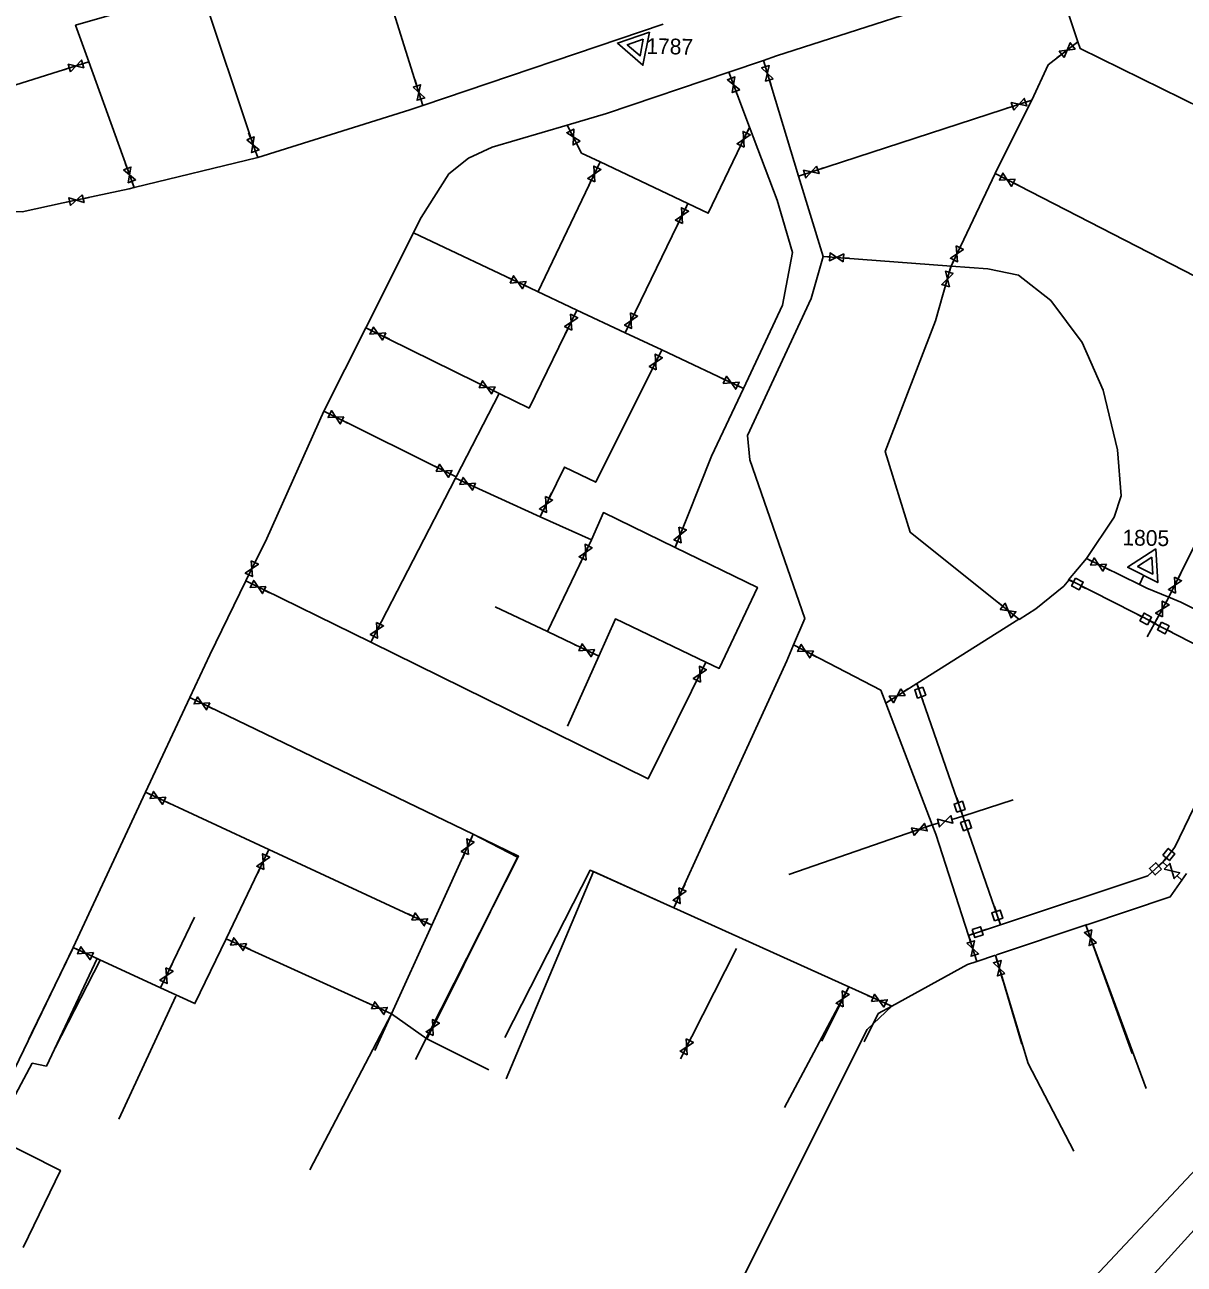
# Model space of a CAD drawing. Extents: x 349903 to 372392, y 368574 to 383062.
# Drawn here: x 362470.3 to 362839.3, y 371926.1 to 372320.7 of the extents above; entities that cross this region are included whole.
import ezdxf

# ---------------------------------------------------------------- set-up
doc = ezdxf.new("R2010")
doc.units = 0
for name, color, linetype in [('Niveau 1', 7, 'Continuous'), ('Niveau 10', 7, 'Continuous'), ('Niveau 2', 7, 'Continuous'), ('Niveau 3', 7, 'Continuous')]:
    doc.layers.add(name, color=color, linetype=linetype)

msp = doc.modelspace()

# ---------------------------------------------------------------- linework, layer by layer
at = {"layer": 'Niveau 1'}
for p, q in [((362805.444, 372315.204), (362803.772, 372313.927)), ((362490.677, 372308.847), (362488.668, 372308.22)), ((362705.358, 372309.317), (362705.968, 372307.303)), ((362800.292, 372311.267), (362798.781, 372310.113)), ((362484.488, 372306.914), (362482.673, 372306.347)), ((362694.347, 372305.592), (362695.081, 372303.62)), ((362595.067, 372301.2), (362594.506, 372303.017)), ((362707.238, 372303.111), (362707.789, 372301.292)), ((362596.98, 372295.005), (362596.359, 372297.016)), ((362696.61, 372299.516), (362697.274, 372297.734)), ((362790.786, 372296.717), (362788.788, 372296.057)), ((362784.629, 372294.684), (362782.824, 372294.087)), ((362642.871, 372288.726), (362643.845, 372286.86)), ((362542.151, 372284.521), (362541.493, 372286.305)), ((362700.947, 372288.086), (362700.029, 372286.192)), ((362544.393, 372278.437), (362543.666, 372280.412)), ((362645.872, 372282.978), (362646.752, 372281.293)), ((362698.121, 372282.251), (362697.292, 372280.539)), ((362502.855, 372274.922), (362502.19, 372276.703)), ((362653.4, 372277.031), (362652.482, 372275.138)), ((362716.495, 372272.477), (362718.496, 372273.128)), ((362722.66, 372274.485), (362724.468, 372275.074)), ((362779.135, 372273.306), (362781.006, 372272.343)), ((362505.124, 372268.848), (362504.388, 372270.819)), ((362650.571, 372271.197), (362649.742, 372269.486)), ((362784.901, 372270.34), (362786.592, 372269.471)), ((362488.854, 372265.294), (362490.713, 372265.694)), ((362482.515, 372263.933), (362484.572, 372264.374)), ((362681.331, 372263.756), (362680.408, 372261.865)), ((362678.488, 372257.928), (362677.655, 372256.219)), ((362767.884, 372249.716), (362768.707, 372251.43)), ((362724.348, 372246.944), (362726.447, 372246.792)), ((362730.815, 372246.476), (362732.711, 372246.339)), ((362765.079, 372243.87), (362765.99, 372245.767)), ((362765.079, 372243.87), (362764.502, 372241.846)), ((362625.31, 372239.612), (362623.589, 372240.419)), ((362631.181, 372236.86), (362629.276, 372237.754)), ((362763.303, 372237.634), (362762.782, 372235.805)), ((362646.021, 372229.865), (362645.101, 372227.973)), ((362664.179, 372228.474), (362665.003, 372230.187)), ((362578.773, 372224.214), (362580.671, 372223.305)), ((362584.622, 372221.415), (362586.337, 372220.595)), ((362643.187, 372224.033), (362642.355, 372222.323)), ((362661.368, 372222.631), (362662.281, 372224.527)), ((362672.993, 372217.152), (362672.06, 372215.266)), ((362670.119, 372211.34), (362669.276, 372209.636)), ((362615.448, 372206.206), (362613.743, 372207.047)), ((362693.115, 372207.655), (362691.394, 372208.462)), ((362698.985, 372204.9), (362697.08, 372205.794)), ((362621.264, 372203.339), (362619.377, 372204.27)), ((362565.47, 372197.694), (362567.345, 372196.738)), ((362571.247, 372194.749), (362572.941, 372193.886)), ((362601.751, 372179.642), (362600.048, 372180.488)), ((362607.558, 372176.757), (362605.674, 372177.694)), ((362607.33, 372176.314), (362609.247, 372175.446)), ((362613.237, 372173.641), (362614.969, 372172.857)), ((362637.098, 372169.922), (362637.923, 372171.635)), ((362634.284, 372164.08), (362635.197, 372165.976)), ((362679.66, 372160.312), (362680.364, 372162.078)), ((362650.612, 372156.662), (362649.704, 372154.764)), ((362677.261, 372154.288), (362678.04, 372156.243)), ((362543.494, 372149.477), (362544.32, 372151.189)), ((362647.815, 372150.812), (362646.995, 372149.097)), ((362808.128, 372150.757), (362810.011, 372149.818)), ((362813.931, 372147.865), (362815.633, 372147.017)), ((362540.677, 372143.637), (362541.592, 372145.532)), ((362540.677, 372143.637), (362542.554, 372142.686)), ((362837.3, 372144.245), (362838.145, 372145.949)), ((362546.462, 372140.71), (362548.158, 372139.851)), ((362834.42, 372138.436), (362833.401, 372136.595)), ((362834.42, 372138.436), (362835.355, 372140.321)), ((362781.534, 372135.548), (362780.049, 372136.735)), ((362583.346, 372129.866), (362584.21, 372131.56)), ((362786.598, 372131.498), (362784.955, 372132.813)), ((362831.281, 372132.763), (362830.362, 372131.099)), ((362580.402, 372124.089), (362581.358, 372125.964)), ((362647.1, 372122.491), (362645.382, 372123.306)), ((362714.946, 372123.279), (362716.806, 372122.296)), ((362652.959, 372119.713), (362651.058, 372120.615)), ((362720.679, 372120.25), (362722.36, 372119.362)), ((362687.029, 372117.794), (362686.097, 372115.907)), ((362684.159, 372111.98), (362683.318, 372110.275)), ((362749.741, 372108.234), (362751.348, 372109.251)), ((362522.808, 372106.511), (362524.701, 372105.592)), ((362528.642, 372103.682), (362530.353, 372102.852)), ((362744.262, 372104.767), (362746.04, 372105.892)), ((362508.747, 372076.346), (362510.656, 372075.46)), ((362514.629, 372073.618), (362516.354, 372072.818)), ((362765.298, 372067.722), (362767.128, 372068.237)), ((362752.938, 372063.817), (362751.145, 372063.186)), ((362759.055, 372065.969), (362757.07, 372065.271)), ((362759.055, 372065.969), (362761.081, 372066.538)), ((362612.976, 372062.964), (362612.12, 372061.042)), ((362547.981, 372058.132), (362547.082, 372056.229)), ((362610.339, 372057.04), (362609.566, 372055.303)), ((362545.211, 372052.269), (362544.399, 372050.55)), ((362833.805, 372052.811), (362832.422, 372054.116)), ((362838.519, 372048.359), (362836.989, 372049.804)), ((362679.603, 372045.408), (362680.407, 372047.131)), ((362676.861, 372039.532), (362677.751, 372041.439)), ((362593.982, 372036.818), (362592.262, 372037.628)), ((362599.847, 372034.053), (362597.944, 372034.951)), ((362807.96, 372034.098), (362808.672, 372032.118)), ((362534.352, 372029.732), (362536.275, 372028.877)), ((362771.327, 372028.691), (362770.759, 372030.506)), ((362810.154, 372027.997), (362810.798, 372026.208)), ((362485.697, 372026.903), (362487.607, 372026.02)), ((362491.584, 372024.185), (362493.31, 372023.388)), ((362540.278, 372027.1), (362542.015, 372026.328)), ((362773.262, 372022.503), (362772.634, 372024.512)), ((362779.161, 372024.474), (362779.764, 372022.458)), ((362516.335, 372019.929), (362517.169, 372021.637)), ((362513.488, 372014.103), (362514.412, 372015.994)), ((362781.02, 372018.262), (362781.566, 372016.441)), ((362732.486, 372014.468), (362731.551, 372012.583)), ((362581.13, 372008.519), (362579.399, 372009.305)), ((362729.606, 372008.659), (362728.761, 372006.955)), ((362740.247, 372010.925), (362738.508, 372011.694)), ((362746.176, 372008.3), (362744.252, 372009.152)), ((362587.035, 372005.84), (362585.119, 372006.71)), ((362602.101, 372005.269), (362601.126, 372003.405)), ((362599.095, 371999.524), (362598.214, 371997.84)), ((362681.943, 371997.286), (362682.806, 371998.98)), ((362681.943, 371997.286), (362682.806, 371998.98)), ((362678.999, 371991.509), (362679.954, 371993.383)), ((362678.999, 371991.509), (362679.954, 371993.383))]:
    msp.add_line(p, q, dxfattribs=at)
for points in [[(362801.065, 372310.262), (362799.527, 372312.262), (362804.531, 372312.91), (362803.005, 372314.92)], [(362484.87, 372305.704), (362484.11, 372308.111), (362489.033, 372307.005), (362488.288, 372309.416)], [(362697.797, 372299.962), (362695.435, 372299.074), (362696.275, 372304.05), (362693.907, 372303.176)], [(362708.45, 372303.483), (362706.038, 372302.744), (362707.186, 372307.657), (362704.768, 372306.933)], [(362593.856, 372300.822), (362596.265, 372301.574), (362595.143, 372296.655), (362597.557, 372297.392)], [(362785.031, 372293.481), (362784.232, 372295.874), (362789.172, 372294.849), (362788.389, 372297.247)], [(362540.962, 372284.079), (362543.327, 372284.959), (362542.471, 372279.986), (362544.841, 372280.851)], [(362646.994, 372283.569), (362644.761, 372282.394), (362644.975, 372287.435), (362642.735, 372286.274)], [(362699.264, 372281.701), (362696.989, 372282.794), (362701.165, 372285.627), (362698.897, 372286.734)], [(362501.669, 372274.475), (362504.03, 372275.365), (362503.195, 372270.389), (362505.562, 372271.264)], [(362651.714, 372270.647), (362649.44, 372271.741), (362653.617, 372274.572), (362651.35, 372275.68)], [(362722.264, 372275.69), (362723.053, 372273.293), (362718.116, 372274.339), (362718.89, 372271.937)], [(362785.477, 372271.47), (362784.33, 372269.222), (362781.599, 372273.465), (362780.437, 372271.224)], [(362488.584, 372266.533), (362489.122, 372264.068), (362484.32, 372265.618), (362484.842, 372263.149)], [(362679.63, 372257.376), (362677.359, 372258.475), (362681.542, 372261.296), (362679.278, 372262.41)], [(362766.739, 372250.261), (362769.018, 372249.176), (362764.852, 372246.328), (362767.124, 372245.229)], [(362730.902, 372247.741), (362730.728, 372245.224), (362726.552, 372248.056), (362726.362, 372245.54)], [(362764.524, 372237.29), (362762.094, 372237.974), (362765.718, 372241.486), (362763.293, 372242.185)], [(362624.776, 372238.462), (362625.839, 372240.75), (362628.725, 372236.611), (362629.803, 372238.892)], [(362663.035, 372229.02), (362665.312, 372227.933), (362661.144, 372225.09), (362663.414, 372223.988)], [(362644.329, 372223.483), (362642.056, 372224.579), (362646.236, 372227.406), (362643.969, 372228.516)], [(362585.165, 372222.561), (362584.083, 372220.281), (362581.231, 372224.444), (362580.135, 372222.171)], [(362671.257, 372210.781), (362668.992, 372211.893), (362673.191, 372214.691), (362670.932, 372215.817)], [(362614.892, 372205.068), (362616, 372207.334), (362618.804, 372203.138), (362619.926, 372205.398)], [(362692.58, 372206.505), (362693.645, 372208.793), (362696.529, 372204.652), (362697.608, 372206.933)], [(362571.819, 372195.881), (362570.68, 372193.629), (362567.933, 372197.862), (362566.78, 372195.617)], [(362601.191, 372178.505), (362602.306, 372180.768), (362605.097, 372176.564), (362606.227, 372178.82)], [(362613.756, 372174.798), (362612.723, 372172.496), (362609.783, 372176.596), (362608.735, 372174.3)], [(362635.953, 372170.468), (362638.23, 372169.381), (362634.061, 372166.539), (362636.331, 372165.436)], [(362678.481, 372160.777), (362680.828, 372159.851), (362676.867, 372156.725), (362679.208, 372155.784)], [(362648.961, 372150.269), (362646.681, 372151.35), (362650.842, 372154.204), (362648.569, 372155.3)], [(362814.493, 372149.001), (362813.375, 372146.74), (362810.589, 372150.947), (362809.457, 372148.692)], [(362542.351, 372150.024), (362544.627, 372148.935), (362540.455, 372146.096), (362542.725, 372144.992)], [(362547.031, 372141.842), (362545.899, 372139.587), (362543.14, 372143.812), (362541.993, 372141.564)], [(362836.162, 372144.805), (362838.426, 372143.691), (362834.225, 372140.897), (362836.482, 372139.769)], [(362780.745, 372134.555), (362782.315, 372136.53), (362784.152, 372131.831), (362785.734, 372133.796)], [(362832.393, 372132.152), (362830.182, 372133.366), (362834.504, 372135.969), (362832.3, 372137.197)], [(362582.215, 372130.438), (362584.466, 372129.299), (362580.234, 372126.552), (362582.479, 372125.399)], [(362646.561, 372121.344), (362647.635, 372123.627), (362650.502, 372119.475), (362651.59, 372121.752)], [(362721.268, 372121.373), (362720.096, 372119.139), (362717.411, 372123.411), (362716.225, 372121.183)], [(362685.298, 372111.422), (362683.032, 372112.532), (362687.229, 372115.333), (362684.969, 372116.457)], [(362529.192, 372104.824), (362528.098, 372102.551), (362525.267, 372106.728), (362524.159, 372104.461)], [(362749.059, 372109.304), (362750.416, 372107.176), (362745.374, 372106.971), (362746.716, 372104.835)], [(362515.159, 372074.77), (362514.105, 372072.478), (362511.202, 372076.605), (362510.133, 372074.319)], [(362764.951, 372068.942), (362765.641, 372066.515), (362760.751, 372067.762), (362761.426, 372065.331)], [(362753.363, 372062.622), (362752.518, 372065), (362757.478, 372064.07), (362756.648, 372066.453)], [(362611.499, 372056.528), (362609.191, 372057.547), (362613.273, 372060.513), (362610.971, 372061.547)], [(362546.36, 372051.731), (362544.075, 372052.802), (362548.223, 372055.675), (362545.944, 372056.76)], [(362832.937, 372051.886), (362834.664, 372053.726), (362836.108, 372048.891), (362837.847, 372050.721)], [(362678.452, 372045.94), (362680.742, 372044.881), (362676.608, 372041.988), (362678.891, 372040.913)], [(362593.445, 372035.669), (362594.514, 372037.955), (362597.39, 372033.809), (362598.474, 372036.088)], [(362811.346, 372028.43), (362808.975, 372027.568), (362809.87, 372032.534), (362807.493, 372031.687)], [(362540.789, 372028.26), (362539.772, 372025.951), (362536.803, 372030.031), (362535.771, 372027.728)], [(362770.118, 372028.309), (362772.524, 372029.07), (362771.42, 372024.146), (362773.83, 372024.892)], [(362492.112, 372025.338), (362491.061, 372023.043), (362488.152, 372027.166), (362487.086, 372024.879)], [(362515.194, 372020.482), (362517.464, 372019.381), (362513.279, 372016.563), (362515.542, 372015.448)], [(362782.234, 372018.63), (362779.819, 372017.899), (362780.983, 372022.808), (362778.563, 372022.092)], [(362730.744, 372008.099), (362728.479, 372009.213), (362732.681, 372012.007), (362730.424, 372013.135)], [(362739.737, 372009.763), (362740.752, 372012.074), (362743.726, 372007.998), (362744.755, 372010.302)], [(362580.61, 372007.363), (362581.645, 372009.664), (362584.582, 372005.56), (362585.632, 372007.855)], [(362600.221, 371998.94), (362597.981, 372000.102), (362602.242, 372002.805), (362600.012, 372003.982)], [(362680.812, 371997.858), (362683.063, 371996.72), (362678.83, 371993.972), (362681.075, 371992.819)], [(362680.812, 371997.858), (362683.063, 371996.72), (362678.83, 371993.972), (362681.075, 371992.819)]]:
    msp.add_lwpolyline(points, close=True, dxfattribs=at)
at = {"layer": 'Niveau 10'}
for p, q in [((362579.032, 372352.421), (362596.98, 372295.005)), ((362490.677, 372308.847), (362453.772, 372297.302)), ((362653.4, 372277.031), (362633.58, 372235.591)), ((362681.331, 372263.756), (362661.368, 372222.631)), ((362631.181, 372236.86), (362593.955, 372254.407)), ((362646.021, 372229.865), (362631.181, 372236.86)), ((362661.368, 372222.631), (362646.021, 372229.865)), ((362672.993, 372217.152), (362661.368, 372222.631)), ((362698.985, 372204.9), (362672.993, 372217.152)), ((362621.264, 372203.339), (362607.558, 372176.757)), ((362565.47, 372197.694), (362607.558, 372176.757)), ((362607.33, 372176.314), (362580.402, 372124.089)), ((362607.558, 372176.757), (362607.33, 372176.314)), ((362650.612, 372156.662), (362636.6, 372127.5)), ((362826.383, 372145.423), (362825.007, 372142.487)), ((362834.42, 372138.436), (362829.807, 372130.063)), ((362636.6, 372127.5), (362620.024, 372135.391)), ((362652.959, 372119.713), (362636.6, 372127.5)), ((362829.807, 372130.063), (362827.458, 372125.797)), ((362768.799, 372068.779), (362754.175, 372111.026)), ((362547.981, 372058.132), (362508.747, 372076.346)), ((362768.799, 372068.779), (362784.87, 372073.992)), ((362767.128, 372068.237), (362768.799, 372068.779)), ((362780.775, 372034.184), (362768.799, 372068.779)), ((362759.055, 372065.969), (362713.453, 372050.181)), ((362612.976, 372062.964), (362599.847, 372034.053)), ((362599.847, 372034.053), (362547.981, 372058.132)), ((362513.488, 372014.103), (362524.282, 372036.571)), ((362599.847, 372034.053), (362587.035, 372005.84)), ((362807.96, 372034.098), (362827.199, 371982.008)), ((362807.96, 372034.098), (362822.709, 371993.212)), ((362534.352, 372029.732), (362587.035, 372005.84)), ((362485.697, 372026.903), (362444.861, 371942.512)), ((362679.003, 371991.508), (362696.817, 372026.648)), ((362779.161, 372024.474), (362787.571, 371996.15)), ((362732.486, 372014.468), (362712.068, 371976.03)), ((362732.486, 372014.468), (362723.989, 371997.144)), ((362518.364, 372011.498), (362500.19, 371972.271)), ((362587.035, 372005.84), (362560.985, 371956.13)), ((362587.035, 372005.84), (362581.728, 371994.153)), ((362587.035, 372005.84), (362598.214, 371997.84)), ((362598.214, 371997.84), (362618.01, 371987.97))]:
    msp.add_line(p, q, dxfattribs=at)
for points in [[(363758.548, 373021.97), (363387.656, 372576.394), (363076.85, 372194.567), (362987.022, 372096.447), (362639.639, 371713.502), (362501.408, 371562.226)], [(362797.375, 372339.552), (362805.444, 372315.204)], [(362786.658, 372335.779), (362780.961, 372333.773), (362709.546, 372310.734), (362705.358, 372309.317)], [(362526.463, 372332.136), (362486.468, 372320.502), (362490.677, 372308.847)], [(362526.463, 372332.136), (362543.088, 372282.102), (362544.393, 372278.437)], [(362673.495, 372320.892), (362596.98, 372295.005)], [(362805.444, 372315.204), (362795.945, 372307.922), (362790.786, 372296.717)], [(362805.444, 372315.204), (362806.153, 372313.063), (362877.34, 372278.055), (362886.07, 372267.956), (362910.619, 372195.537), (362908.232, 372180.436), (362896.579, 372157.215)], [(362490.677, 372308.847), (362505.124, 372268.848)], [(362705.358, 372309.317), (362694.347, 372305.592)], [(362705.358, 372309.317), (362716.495, 372272.477)], [(362694.347, 372305.592), (362655.434, 372292.43), (362642.871, 372288.726)], [(362694.347, 372305.592), (362700.947, 372288.086)], [(362790.786, 372296.717), (362716.495, 372272.477)], [(362790.786, 372296.717), (362781.328, 372277.9), (362779.135, 372273.306)], [(362596.98, 372295.005), (362592.864, 372293.613), (362544.393, 372278.437)], [(362642.871, 372288.726), (362619.034, 372281.699), (362611.483, 372278.228), (362605.191, 372273.178), (362596.382, 372259.292), (362578.773, 372224.214)], [(362653.4, 372277.031), (362647.484, 372279.844), (362642.871, 372288.726)], [(362700.947, 372288.086), (362687.805, 372260.679), (362681.331, 372263.756)], [(362700.947, 372288.086), (362709.703, 372264.861), (362714.569, 372248.135), (362711.441, 372231.409), (362698.985, 372204.9)], [(362544.393, 372278.437), (362505.124, 372268.848)], [(362681.331, 372263.756), (362653.4, 372277.031)], [(362716.495, 372272.477), (362724.348, 372246.944)], [(362779.135, 372273.306), (362765.079, 372243.87)], [(362779.135, 372273.306), (362842.837, 372240.518), (362846.217, 372237.412), (362861.737, 372193.75), (362860.763, 372191.636), (362834.42, 372138.436)], [(362505.124, 372268.848), (362503.548, 372268.463), (362482.515, 372263.933)], [(362482.515, 372263.933), (362469.494, 372261.129), (362436.46, 372261.469), (362432.816, 372262.342)], [(362724.348, 372246.944), (362720.556, 372233.487), (362700.312, 372189.945), (362701.056, 372182.18), (362718.502, 372131.679), (362714.946, 372123.279)], [(362724.348, 372246.944), (362765.079, 372243.87)], [(362765.079, 372243.87), (362764.992, 372243.687), (362760.12, 372226.436), (362744.104, 372184.843), (362752.081, 372159.149), (362786.598, 372131.498)], [(362765.079, 372243.87), (362776.743, 372242.99), (362786.487, 372240.979), (362796.805, 372232.935), (362806.836, 372219.567), (362813.427, 372204.329), (362818.013, 372185.354), (362819.159, 372170.691), (362816.994, 372163.919), (362808.128, 372150.757)], [(362646.021, 372229.865), (362630.799, 372198.655), (362621.264, 372203.339)], [(362578.773, 372224.214), (362565.47, 372197.694)], [(362621.264, 372203.339), (362578.773, 372224.214)], [(362672.993, 372217.152), (362652.003, 372175.038), (362642.013, 372179.886), (362634.284, 372164.08)], [(362698.985, 372204.9), (362688.847, 372183.323), (362677.261, 372154.288)], [(362565.47, 372197.694), (362547.304, 372157.164), (362540.677, 372143.637)], [(362607.33, 372176.314), (362634.284, 372164.08)], [(362634.284, 372164.08), (362650.612, 372156.662)], [(362650.612, 372156.662), (362654.436, 372165.379), (362677.261, 372154.288)], [(362677.261, 372154.288), (362703.446, 372141.563), (362691.28, 372115.76), (362687.029, 372117.794)], [(362808.128, 372150.757), (362802.473, 372144.026)], [(362808.128, 372150.757), (362825.007, 372142.487)], [(362540.677, 372143.637), (362529.119, 372120.049), (362522.808, 372106.511)], [(362580.402, 372124.089), (362540.677, 372143.637)], [(362802.596, 372143.899), (362800.94, 372141.927), (362792.055, 372134.739), (362786.721, 372131.371)], [(362802.97, 372143.892), (362830.304, 372129.929)], [(362825.007, 372142.487), (362827.392, 372141.318), (362834.42, 372138.436)], [(362834.42, 372138.436), (362838.165, 372136.9), (362866.894, 372122.316)], [(362687.029, 372117.794), (362658.259, 372131.556), (362652.959, 372119.713)], [(362786.598, 372131.498), (362754.175, 372111.026)], [(362829.807, 372130.063), (362863.647, 372112.697)], [(362687.029, 372117.794), (362668.687, 372080.647), (362580.402, 372124.089)], [(362714.946, 372123.279), (362712.791, 372118.191), (362687.957, 372063.963), (362676.861, 372039.532)], [(362714.946, 372123.279), (362742.709, 372108.839), (362744.262, 372104.767)], [(362652.959, 372119.713), (362642.965, 372097.384)], [(362866.894, 372122.316), (362836.314, 372058.871), (362833.081, 372054.731), (362832.422, 372054.116)], [(362754.175, 372111.026), (362744.262, 372104.767)], [(362522.808, 372106.511), (362508.747, 372076.346)], [(362522.808, 372106.511), (362612.976, 372062.964)], [(362744.262, 372104.767), (362759.055, 372065.969)], [(362974.148, 372096.193), (362775.185, 371884.097), (362449.64, 371533.04)], [(362508.747, 372076.346), (362485.697, 372026.903)], [(362759.055, 372065.969), (362760.182, 372063.013), (362770.587, 372030.79)], [(362612.976, 372062.964), (362627.408, 372055.994), (362594.606, 371991.273)], [(362612.976, 372062.964), (362627.059, 372055.675), (362601.398, 372004.052), (362598.214, 371997.84)], [(362547.981, 372058.132), (362534.352, 372029.732)], [(362623.014, 371998.289), (362650.2, 372051.536), (362676.861, 372039.532)], [(362832.422, 372054.116), (362827.66, 372049.801), (362780.775, 372034.184)], [(362676.861, 372039.532), (362651.298, 372051.183), (362623.521, 371985.096)], [(362838.519, 372048.359), (362834.832, 372043.077), (362807.96, 372034.098)], [(362840.022, 372050.511), (362838.519, 372048.359)], [(362676.861, 372039.532), (362732.486, 372014.468)], [(362780.775, 372034.184), (362770.587, 372030.79)], [(362808.337, 372034.216), (362779.538, 372024.592)], [(362534.352, 372029.732), (362524.433, 372009.062), (362513.488, 372014.103)], [(362770.587, 372030.79), (362773.262, 372022.503)], [(362485.697, 372026.903), (362485.483, 372026.443), (362472.44, 371999.565), (362471.557, 371997.755)], [(362513.488, 372014.103), (362485.697, 372026.903)], [(362779.161, 372024.474), (362773.262, 372022.503)], [(362779.161, 372024.474), (362789.56, 371990.001), (362804.098, 371962.154)], [(362493.31, 372023.388), (362477.138, 371989.2), (362472.649, 371990.098), (362460.081, 371966.742), (362481.626, 371955.962), (362469.77, 371931.456)], [(362494.253, 372022.91), (362479.989, 371995.027)], [(362773.262, 372022.503), (362770.322, 372021.521), (362746.176, 372008.3)], [(362732.486, 372014.468), (362746.176, 372008.3)], [(362746.176, 372008.3), (362738.378, 372000.878), (362696.184, 371916.436)], [(362746.176, 372008.3), (362741.824, 372005.917), (362737.368, 371996.864)]]:
    msp.add_lwpolyline(points, dxfattribs=at)
at = {"layer": 'Niveau 2'}
for points in [[(362669.057, 372318.315), (362666.991, 372307.757), (362658.881, 372314.825)], [(362667.124, 372316.044), (362666.09, 372310.767), (362662.036, 372314.303)], [(362830.282, 372153.833), (362830.862, 372143.09), (362821.269, 372147.959)], [(362828.963, 372151.158), (362829.252, 372145.788), (362824.456, 372148.225)]]:
    msp.add_lwpolyline(points, close=True, dxfattribs=at)
at = {"layer": 'Niveau 3'}
for p, q in [((362804.027, 372143.237), (362802.473, 372144.026)), ((362807.951, 372141.244), (362806.503, 372141.979)), ((362824.391, 372132.963), (362825.823, 372132.197)), ((362828.271, 372130.885), (362829.807, 372130.063)), ((362831.361, 372129.275), (362829.807, 372130.063)), ((362835.286, 372127.284), (362833.837, 372128.018)), ((362754.761, 372109.385), (362754.175, 372111.026)), ((362756.24, 372105.24), (362755.694, 372106.769)), ((362766.879, 372074.615), (362767.387, 372073.072)), ((362768.254, 372070.434), (362768.799, 372068.779)), ((362769.381, 372067.137), (362768.799, 372068.779)), ((362770.851, 372062.988), (362770.308, 372064.519)), ((362833.525, 372055.465), (362832.422, 372054.116)), ((362836.314, 372058.871), (362835.284, 372057.613)), ((362831.133, 372052.944), (362832.422, 372054.116)), ((362827.874, 372049.984), (362829.077, 372051.077)), ((362778.872, 372040.026), (362779.375, 372038.481)), ((362780.235, 372035.84), (362780.775, 372034.184)), ((362776.408, 372032.757), (362774.869, 372032.237)), ((362772.237, 372031.348), (362770.587, 372030.79))]:
    msp.add_line(p, q, dxfattribs=at)
for points in [[(362804.663, 372144.492), (362803.42, 372142.044), (362805.876, 372140.796), (362807.119, 372143.245)], [(362827.607, 372129.644), (362828.904, 372132.065), (362826.475, 372133.366), (362825.179, 372130.945)], [(362831.997, 372130.531), (362830.754, 372128.082), (362833.212, 372126.835), (362834.453, 372129.284)], [(362756.086, 372109.859), (362753.499, 372108.936), (362754.425, 372106.342), (362757.012, 372107.264)], [(362766.918, 372069.994), (362769.527, 372070.852), (362768.666, 372073.468), (362766.057, 372072.61)], [(362770.707, 372067.607), (362768.118, 372066.69), (362769.039, 372064.094), (362771.627, 372065.011)], [(362832.436, 372056.355), (362834.562, 372054.616), (362836.304, 372056.748), (362834.181, 372058.488)], [(362832.079, 372051.903), (362830.232, 372053.936), (362828.195, 372052.083), (362830.04, 372050.05)], [(362778.897, 372035.404), (362781.509, 372036.255), (362780.655, 372038.874), (362778.044, 372038.023)], [(362771.786, 372032.681), (362772.666, 372030.079), (362775.275, 372030.961), (362774.396, 372033.563)]]:
    msp.add_lwpolyline(points, close=True, dxfattribs=at)

# ---------------------------------------------------------------- texts
at = {"layer": 'Niveau 2'}
for s, p in [('1787', (362668.06, 372311.404)), ('1805', (362819.565, 372154.95))]:
    msp.add_text(s, height=5, rotation=359, dxfattribs=at).set_placement(p)

doc.saveas('drawing.dxf')
